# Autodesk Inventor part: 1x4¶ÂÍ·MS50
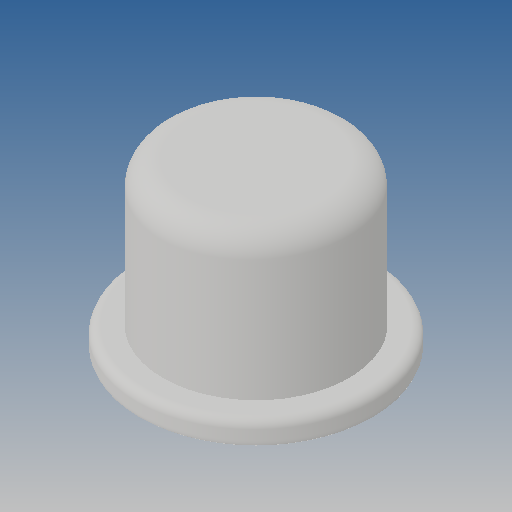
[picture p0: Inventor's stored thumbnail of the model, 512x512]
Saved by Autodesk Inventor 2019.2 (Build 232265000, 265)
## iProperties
Created: 2013-07
Part Number: 1x4¶ÂÍ·MS50
Material: Ogólny
Document SubType Name: Modeling
Designer: CADENGINEERING4
Density: 1 g/cm^3
Appearance: Domyślna
Author: CADENGINEERING4
Revision Number: ÈÎºÎ
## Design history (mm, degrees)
feature "Ô²½Ç1"
node "Bryła1"
